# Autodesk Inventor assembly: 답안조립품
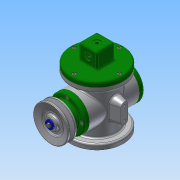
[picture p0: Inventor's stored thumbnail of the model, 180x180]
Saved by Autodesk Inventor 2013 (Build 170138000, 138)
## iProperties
Created: 2018-02
Part Number: 답안조립품
Document SubType Name: Assembly
Designer: Administrator
Author: Administrator
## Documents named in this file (18)
- C:\Users\Administrator\Desktop\480208V1016\답안조립품.iam
- C:\Users\Administrator\Desktop\480208V1016\본체.ipt
- C:\Users\Administrator\Desktop\480208V1016\링크.ipt
- C:\Users\Administrator\Desktop\480208V1016\베어링 17 x 40 x 12.ipt
- C:\Users\Administrator\Desktop\480208V1016\슬라이더.ipt
- C:\Users\Administrator\Desktop\480208V1016\클레비스 핀 6 x 22.ipt
- 클레비스 핀 6 x 22.ipt
- C:\Users\Administrator\Desktop\480208V1016\편심축.ipt
- C:\Users\Administrator\Desktop\480208V1016\E-링.ipt
- C:\Users\Administrator\Desktop\480208V1016\뒤커버.ipt
- C:\Users\Administrator\Desktop\480208V1016\앞커버.ipt
- C:\Users\Administrator\Desktop\480208V1016\볼트 M4 x 8.ipt
- C:\Users\Administrator\Desktop\480208V1016\덮개.ipt
- C:\Users\Administrator\Desktop\480208V1016\V-벨트풀리.ipt
- C:\Users\Administrator\Desktop\480208V1016\키 4 x 4 x 12.ipt
- C:\Users\Administrator\Desktop\480208V1016\볼트 M4 x 10.ipt
- C:\Users\Administrator\Desktop\480208V1016\와셔 4x16.ipt
- C:\Users\Administrator\Desktop\480208V1016\오일 실 17 30 8.ipt
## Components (2 placed, 2 different names)
1. E-링:1
2. V-벨트풀리:1 — 플러쉬:2
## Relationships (1: Flush 1)
- 플러쉬:2 [Flush]: V-벨트풀리:1
